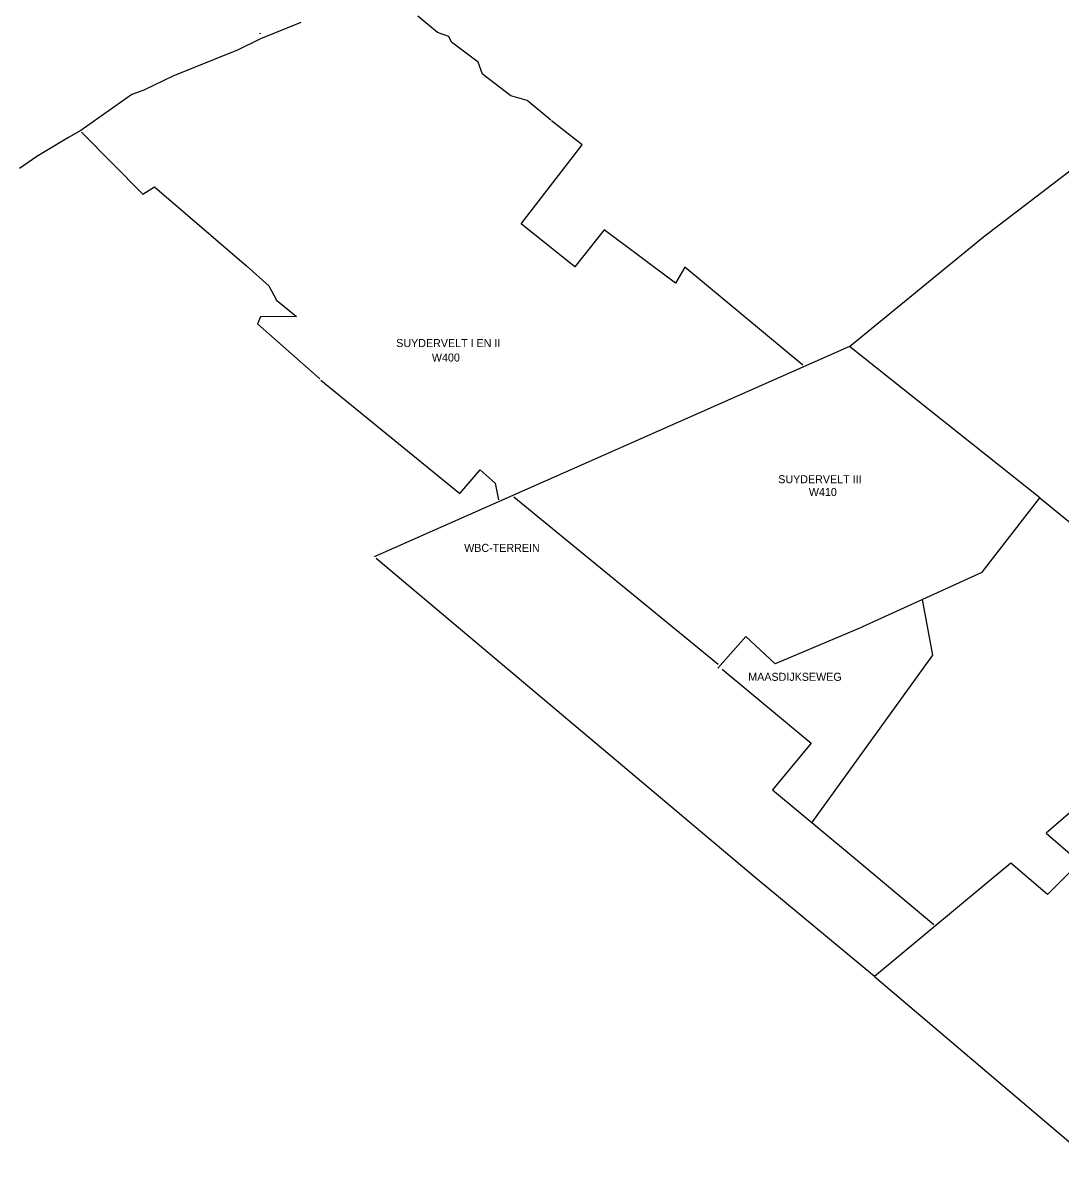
# Model space of a CAD drawing. Extents: x 69068 to 80855, y 440023 to 451362.
# Drawn here: x 78102 to 79268, y 447576 to 448851 of the extents above; entities that cross this region are included whole.
import ezdxf

# ---------------------------------------------------------------- set-up
doc = ezdxf.new("R2010")
doc.units = 0
for name, color, linetype in [('Bemalingsgebiedsgrens', 7, 'Continuous'), ('Bemalingsgebiedsnummer', 7, 'Continuous'), ('RIO_Leidingen', 7, 'Continuous')]:
    doc.layers.add(name, color=color, linetype=linetype)

msp = doc.modelspace()

# ---------------------------------------------------------------- linework, layer by layer
at = {"layer": 'Bemalingsgebiedsgrens'}
msp.add_line((78654, 448317.9), (78883.6, 448129.7), dxfattribs=at)
for points in [[(78414.3, 448851.4), (78368.9, 448832.8), (78344, 448820.6), (78270.3, 448790.9), (78237.7, 448775.3), (78224.2, 448770.2), (78166.9, 448729.8), (78153.1, 448722.1), (78117.5, 448700.6), (78098.1, 448687.3)], [(78695.6, 448741.4), (78668.7, 448763.5), (78650.3, 448768.8), (78618.7, 448793.3), (78613.8, 448806.6), (78583.7, 448829.3), (78580.8, 448835.6), (78568.1, 448840.2), (78546, 448858.6)], [(78369, 448839.1), (78367.8, 448838.6)], [(79031.1, 448486.9), (79181.7, 448610.2), (79493.5, 448848.8)], [(78978.7, 448466.2), (78846, 448576.1), (78835.5, 448558.3), (78755.5, 448618.1), (78722.3, 448576.6), (78661.9, 448625), (78730.8, 448713.9), (78696.3, 448740.7)], [(78167.7, 448728.1), (78236.9, 448658.5), (78249.9, 448666.4), (78353.4, 448577.9), (78378.3, 448555.3), (78387, 448539.1), (78409.6, 448520.9), (78369.2, 448520.5), (78365.7, 448512.6), (78435.6, 448450.5)], [(79245.3, 448316.8), (79031.1, 448486.9), (78496.7, 448250.7)], [(78437, 448449.3), (78593.1, 448321.6), (78616, 448348.5), (78633, 448333.5), (78636.7, 448314.8)], [(79046.2, 448172.2), (79180.3, 448233.2), (79245.3, 448316.8), (79465.2, 448137.5)], [(79059.3, 447778.7), (78925.1, 447889.8), (78499, 448248.7)], [(78988.9, 447951.6), (79124.8, 448140), (79113.2, 448202.7)], [(79046.1, 448172), (78947.7, 448130.2), (78914.8, 448160.8), (78883, 448125.4)], [(79465.2, 448137.5), (79474.2, 448130), (79326.7, 448001.5), (79348.4, 447983.6), (79322.2, 447956.2), (79290.4, 447972.9), (79252.2, 447939.7), (79290.1, 447907.1), (79253.8, 447870.8), (79212.7, 447906.1), (79059.3, 447778.7), (79297.7, 447576.4)], [(78888.1, 448124.4), (78988.2, 448040.9), (78944.5, 447988.6), (79033.3, 447914.6), (79126, 447837.2)]]:
    msp.add_lwpolyline(points, dxfattribs=at)

# ---------------------------------------------------------------- texts
at = {"layer": 'Bemalingsgebiedsnummer'}
for s, p in [('W400', (78561.7, 448470.1)), ('W410', (78985.5, 448318.9))]:
    msp.add_text(s, height=9, dxfattribs=at).set_placement(p)
at = {"layer": 'RIO_Leidingen'}
for s, p in [('SUYDERVELT I EN II', (78521.6, 448486.4)), ('SUYDERVELT III', (78951.1, 448333.3)), ('WBC-TERREIN', (78598, 448256.1)), ('MAASDIJKSEWEG', (78917.4, 448111.1))]:
    msp.add_text(s, height=9, dxfattribs=at).set_placement(p)

doc.saveas('drawing.dxf')
